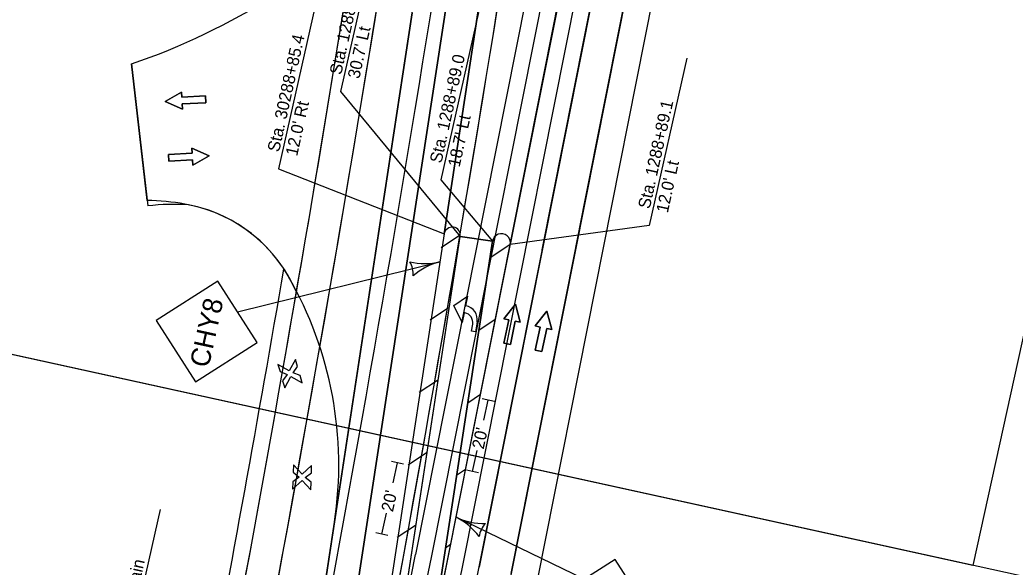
# Model space of a CAD drawing. Extents: x 14104283 to 14120882, y 8635219 to 8671666.
# Drawn here: x 14107792.5 to 14108160.1, y 8639735.9 to 8639938.3 of the extents above; entities that cross this region are included whole.
import ezdxf

# ---------------------------------------------------------------- set-up
doc = ezdxf.new("R2010")
doc.units = 0
for name, color, linetype in [('Cell', 7, 'Continuous'), ('dsnNonPlotable', 7, 'Continuous'), ('dsnPaintExistingBrokenLaneLineWhite', 7, 'Continuous'), ('dsnPaintExistingEdgeLineRightWhite', 7, 'Continuous'), ('dsnPaintPlaceBrokenLaneLineWhite', 7, 'Continuous'), ('dsnPaintPlaceBrokenLaneWhite', 7, 'Continuous'), ('dsnPaintPlaceChannelizingLaneWhite', 7, 'Continuous'), ('dsnPaintPlaceChannelizingLaneYellow', 7, 'Continuous'), ('dsnPaintPlaceEdgeLineRightWhite', 7, 'Continuous'), ('dsnPaintRemoveEdgeLineWhite', 7, 'Continuous'), ('dsnPaintRemoveEdgeLineYellow', 7, 'Continuous'), ('dsnShadingPaved', 7, 'Continuous'), ('dsnStdLabel', 7, 'Continuous'), ('dsnStgShadingPrevPav', 7, 'Continuous'), ('Level 2', 7, 'Continuous'), ('Level 5', 7, 'Continuous'), ('Text', 7, 'Continuous')]:
    doc.layers.add(name, color=color, linetype=linetype)

msp = doc.modelspace()

# ---------------------------------------------------------------- linework, layer by layer
at = {"layer": 'Cell'}
for p, q in [((14107957.11, 8639832.53), (14107957.29, 8639832.5)), ((14107956.89, 8639829.91), (14107956.58, 8639829.95)), ((14107892.01, 8639808.57), (14107887.84, 8639810.89)), ((14107887.84, 8639810.89), (14107888.6, 8639808.24)), ((14107894.33, 8639812.75), (14107892.01, 8639808.57)), ((14107895.09, 8639810.1), (14107894.33, 8639812.75)), ((14107888.6, 8639808.24), (14107891.24, 8639807.18)), ((14107891.24, 8639807.18), (14107889.56, 8639804.88)), ((14107893.4, 8639807.8), (14107895.09, 8639810.1)), ((14107896.05, 8639806.74), (14107893.4, 8639807.8)), ((14107896.81, 8639804.09), (14107896.05, 8639806.74)), ((14107889.56, 8639804.88), (14107890.32, 8639802.24)), ((14107890.32, 8639802.24), (14107892.63, 8639806.41)), ((14107892.63, 8639806.41), (14107896.81, 8639804.09)), ((14107893.54, 8639773.76), (14107893.45, 8639771.01)), ((14107896.8, 8639770.27), (14107893.54, 8639773.76)), ((14107900.29, 8639773.53), (14107896.8, 8639770.27)), ((14107900.2, 8639770.79), (14107900.29, 8639773.53)), ((14107893.45, 8639771.01), (14107895.64, 8639769.19)), ((14107897.89, 8639769.11), (14107900.2, 8639770.79)), ((14107893.24, 8639764.76), (14107896.73, 8639768.02)), ((14107893.33, 8639767.51), (14107893.24, 8639764.76)), ((14107895.64, 8639769.19), (14107893.33, 8639767.51)), ((14107896.73, 8639768.02), (14107899.99, 8639764.54)), ((14107900.08, 8639767.29), (14107897.89, 8639769.11)), ((14107899.99, 8639764.54), (14107900.08, 8639767.29))]:
    msp.add_line(p, q, dxfattribs=at)
for points in [[(14107952.78, 8639832.67), (14107957.86, 8639836.14), (14107957.11, 8639832.53)], [(14107952.78, 8639832.67), (14107957.86, 8639836.14), (14107957.11, 8639832.53)], [(14107956.58, 8639829.95), (14107955.83, 8639826.35), (14107952.78, 8639832.67)], [(14107956.58, 8639829.95), (14107955.83, 8639826.35), (14107952.78, 8639832.67)], [(14107957.11, 8639832.53), (14107957.29, 8639832.5)], [(14107956.89, 8639829.91), (14107956.58, 8639829.95)], [(14107961.41, 8639826.54), (14107960.84, 8639822.91), (14107959.37, 8639823.14), (14107959.77, 8639825.73)], [(14107961.41, 8639826.54), (14107960.84, 8639822.91), (14107959.37, 8639823.14), (14107959.77, 8639825.73)]]:
    msp.add_lwpolyline(points, dxfattribs=at)
for centre, major_axis in [((14107956.49, 8639827.31), (-0.81, -5.19)), ((14107956.49, 8639827.31), (-0.81, -5.19)), ((14107956.32, 8639826.27), (-0.57, -3.64)), ((14107956.32, 8639826.27), (-0.57, -3.64))]:
    msp.add_ellipse(centre, major_axis=major_axis, ratio=0.9474, start_param=1.570796, end_param=3.141593, dxfattribs=at)
at = {"layer": 'dsnNonPlotable'}
for points in [[(14107490.45, 8639880.3), (14107826.84, 8641411.28), (14108813.31, 8641194.53), (14108476.92, 8639663.55)], [(14107651.31, 8639844.94), (14107987.7, 8641375.92), (14108480.93, 8641267.54), (14108144.54, 8639736.56)]]:
    msp.add_lwpolyline(points, close=True, dxfattribs=at)
at = {"layer": 'dsnPaintExistingBrokenLaneLineWhite'}
msp.add_line((14107897.23, 8639597.8), (14108002.8, 8640289.8), dxfattribs=at)
at = {"layer": 'dsnPaintExistingEdgeLineRightWhite'}
msp.add_line((14107908.71, 8639752.63), (14107885.37, 8639599.61), dxfattribs=at)
for centre, radius, start, end in [((14107752.7, 8640158.5), 250, 288.9195, 302.3186), ((14107838.11, 8639781.51), 90, 80.198, 89.1076), ((14107844.07, 8639816), 55, 29.809, 80.198), ((14107770.31, 8639773.74), 140, 351.326, 29.809)]:
    msp.add_arc(centre, radius, start, end, dxfattribs=at)
at = {"layer": 'dsnPaintPlaceBrokenLaneLineWhite'}
msp.add_lwpolyline([(14107985.48, 8639853.32), (14108001.11, 8639932.06), (14108016.73, 8640010.8), (14108028.7, 8640069.55), (14108040.67, 8640128.3), (14108053.24, 8640186.93), (14108065.81, 8640245.56), (14108082.44, 8640321.29), (14108099.08, 8640397.01)], dxfattribs=at)
at = {"layer": 'dsnPaintPlaceBrokenLaneWhite'}
msp.add_lwpolyline([(14107843.64, 8639178.31), (14107884.58, 8639364.68), (14107924.33, 8639550.14), (14107962.2, 8639735.99), (14107989.47, 8639873.39), (14108016.73, 8640010.79)], dxfattribs=at)
at = {"layer": 'dsnPaintPlaceChannelizingLaneWhite'}
for p, q in [((14107944.41, 8639708.12), (14107967.03, 8639856.41)), ((14107973.63, 8639855.23), (14107966.08, 8639850.19)), ((14107968.12, 8639827.49), (14107961.99, 8639823.39)), ((14107962.62, 8639799.75), (14107957.91, 8639796.59)), ((14107957.11, 8639772), (14107953.82, 8639769.8)), ((14107951.61, 8639744.26), (14107949.73, 8639743))]:
    msp.add_line(p, q, dxfattribs=at)
msp.add_lwpolyline([(14107944.41, 8639708.12), (14107950.42, 8639738.27), (14107973.63, 8639855.23)], dxfattribs=at)
msp.add_arc((14107970.34, 8639855.88), 3.35, 348.776, 171.0218, dxfattribs=at)
at = {"layer": 'dsnPaintPlaceChannelizingLaneYellow'}
for p, q in [((14107898.55, 8639487.12), (14107955.17, 8639858.22)), ((14107949.23, 8639859.12), (14107909.09, 8639595.99)), ((14107954.94, 8639858.56), (14107948.17, 8639854.04)), ((14107950.85, 8639831.77), (14107944.08, 8639827.24)), ((14107946.76, 8639804.97), (14107939.99, 8639800.45)), ((14107942.67, 8639778.18), (14107935.91, 8639773.65)), ((14107938.59, 8639751.38), (14107931.82, 8639746.86))]:
    msp.add_line(p, q, dxfattribs=at)
msp.add_arc((14107952.2, 8639858.67), 3, 351.326, 171.326, dxfattribs=at)
at = {"layer": 'dsnPaintPlaceEdgeLineRightWhite'}
msp.add_line((14107973.96, 8639733.6), (14107997.25, 8639850.98), dxfattribs=at)
msp.add_lwpolyline([(14107997.25, 8639850.98), (14108001.23, 8639871.02), (14108028.5, 8640008.43), (14108052.42, 8640125.85), (14108077.53, 8640243.01), (14108094.16, 8640318.73), (14108110.8, 8640394.44)], dxfattribs=at)
at = {"layer": 'dsnPaintRemoveEdgeLineWhite'}
msp.add_lwpolyline([(14107811.17, 8639057.08), (14107844.94, 8639211.53), (14107878.72, 8639365.97), (14107918.46, 8639551.34), (14107956.3, 8639737.1), (14108010.84, 8640011.94), (14108059.95, 8640246.87), (14108093.19, 8640398.18)], dxfattribs=at)
at = {"layer": 'dsnPaintRemoveEdgeLineYellow'}
msp.add_lwpolyline([(14107799.44, 8639059.65), (14107867, 8639368.55), (14107944.53, 8639739.44), (14107999.07, 8640014.27), (14108048.23, 8640249.45), (14108081.5, 8640400.87)], dxfattribs=at)
at = {"layer": 'dsnShadingPaved'}
for p, q in [((14107885.37, 8639599.61), (14107990.94, 8640291.61)), ((14108002.8, 8640289.8), (14107897.23, 8639597.8)), ((14108004.96, 8640013.11), (14107973.63, 8639855.23)), ((14107897.23, 8639597.8), (14107955.22, 8639977.91)), ((14107949.24, 8639859.12), (14107967.08, 8639976.1)), ((14107967.08, 8639976.1), (14107949.24, 8639859.12)), ((14107937.44, 8639940.91), (14107908.71, 8639752.63)), ((14107839.51, 8639871.5), (14107833.76, 8639922)), ((14107897.98, 8639483.38), (14107955.17, 8639858.22)), ((14107949.23, 8639859.12), (14107909.09, 8639595.99)), ((14107967.03, 8639856.41), (14107955.17, 8639858.22)), ((14107955.17, 8639858.22), (14107967.03, 8639856.41)), ((14107967.03, 8639856.41), (14107944.41, 8639708.12))]:
    msp.add_line(p, q, dxfattribs=at)
for points in [[(14107831.92, 8639180.86), (14107872.85, 8639367.2), (14107912.58, 8639552.57), (14107950.43, 8639738.33), (14108004.96, 8640013.11)], [(14108028.5, 8640008.43), (14107973.96, 8639733.6), (14107936.08, 8639547.66), (14107896.3, 8639362.11), (14107855.36, 8639175.71)]]:
    msp.add_lwpolyline(points, dxfattribs=at)
for centre, radius, start, end in [((14107752.7, 8640158.5), 250, 288.9195, 302.3186), ((14107838.11, 8639781.51), 90, 80.198, 89.1076), ((14107844.07, 8639816), 55, 29.809, 80.198), ((14107952.2, 8639858.67), 3, 351.326, 171.326), ((14107970.34, 8639855.88), 3.35, 348.776, 171.0218), ((14107770.31, 8639773.74), 140, 351.326, 29.809)]:
    msp.add_arc(centre, radius, start, end, dxfattribs=at)
at = {"layer": 'dsnStdLabel'}
for p, q in [((14107872.9, 8639830.31), (14107947.66, 8639848.82)), ((14108000.99, 8639731.5), (14107953.61, 8639754.35))]:
    msp.add_line(p, q, dxfattribs=at)
for points in [[(14107857.43, 8639804.39), (14107880.18, 8639818.94), (14107865.63, 8639841.69), (14107842.88, 8639827.14)], [(14108004.17, 8639701.48), (14108026.91, 8639716.03), (14108012.36, 8639738.77), (14107989.62, 8639724.22)]]:
    msp.add_lwpolyline(points, close=True, dxfattribs=at)
for centre, radius, start, end in [((14107942.14, 8639871.1), 22.95, 255.8346, 283.9059), ((14107928.98, 8639844.2), 8.86, 356.1715, 31.64), ((14107953.17, 8639826.54), 22.95, 103.9057, 131.977), ((14107943.64, 8639733.68), 22.95, 36.1773, 64.2486), ((14107963.58, 8639775.02), 22.95, 244.2484, 272.3197), ((14107970.94, 8639745.99), 8.86, 136.5142, 171.9827)]:
    msp.add_arc(centre, radius, start, end, dxfattribs=at)
at = {"layer": 'dsnStgShadingPrevPav'}
for p, q in [((14107993.19, 8640015.44), (14107938.65, 8639740.6)), ((14107993.19, 8640015.44), (14107938.65, 8639740.6)), ((14107950.42, 8639738.27), (14108004.96, 8640013.11)), ((14108016.73, 8640010.77), (14107962.19, 8639735.93)), ((14108016.73, 8640010.77), (14107962.19, 8639735.93)), ((14107983.77, 8639731.65), (14108038.31, 8640006.49)), ((14107950.42, 8639738.27), (14107992.68, 8639951.24)), ((14107833.76, 8639922), (14107839.82, 8639869.51))]:
    msp.add_line(p, q, dxfattribs=at)
for centre, radius, start, end in [((14098576.76, 8641447.78), 9468, 347.807255, 351.672846), ((14098576.76, 8641447.78), 9456, 348.449343, 351.672846), ((14098576.76, 8641447.78), 9468, 348.194582, 351.672846), ((14098576.76, 8641447.78), 9488, 348.202524, 351.672846), ((14098576.76, 8641447.78), 9488, 348.202524, 351.672846), ((14098576.76, 8641447.78), 9512, 348.176197, 351.653537), ((14098576.76, 8641447.78), 9512, 348.212012, 351.653537), ((14098576.76, 8641447.78), 9456, 350.195701, 351.23682), ((14107752.7, 8640158.5), 250, 288.9195, 302.3186), ((14107849.81, 8639782.85), 87.24, 86.7296, 96.5795), ((14107844.07, 8639816), 55, 23.1027, 78.7566), ((14098576.76, 8641447.78), 9450, 348.220778, 350.242299), ((14107844.07, 8639816), 55, 23.1027, 33.2753), ((14098576.76, 8641447.78), 9456, 348.449343, 350.195701), ((14089678.7, 8643364.11), 18616, 348.014807, 348.776036), ((14089678.7, 8643364.11), 18616, 348.014807, 348.776036), ((14089678.7, 8643364.11), 18628, 347.714997, 348.776036), ((14089678.7, 8643364.11), 18628, 347.714933, 348.776036)]:
    msp.add_arc(centre, radius, start, end, dxfattribs=at)
at = {"layer": 'Level 2'}
for points in [[(14107861.24, 8639907.67), (14107861.11, 8639910.16), (14107852.37, 8639909.7), (14107852.27, 8639911.57), (14107846.19, 8639908.12), (14107852.6, 8639905.33), (14107852.5, 8639907.2)], [(14107847.44, 8639888.53), (14107847.57, 8639886.03), (14107856.31, 8639886.5), (14107856.41, 8639884.62), (14107862.49, 8639888.08), (14107856.08, 8639890.86), (14107856.18, 8639888.99)], [(14107971.24, 8639818.81), (14107973.69, 8639818.29), (14107975.5, 8639826.85), (14107977.34, 8639826.46), (14107975.57, 8639833.22), (14107971.22, 8639827.76), (14107973.06, 8639827.37)], [(14107982.87, 8639816.15), (14107985.32, 8639815.63), (14107987.13, 8639824.19), (14107988.96, 8639823.8), (14107987.2, 8639830.57), (14107982.85, 8639825.1), (14107984.68, 8639824.71)]]:
    msp.add_lwpolyline(points, close=True, dxfattribs=at)
at = {"layer": 'Level 5'}
for points in [[(14107852.5, 8639907.2), (14107852.6, 8639905.33), (14107846.19, 8639908.12), (14107852.27, 8639911.57), (14107852.37, 8639909.7), (14107861.11, 8639910.16), (14107861.24, 8639907.67), (14107852.5, 8639907.2)], [(14107856.18, 8639888.99), (14107856.08, 8639890.86), (14107862.49, 8639888.08), (14107856.41, 8639884.62), (14107856.31, 8639886.5), (14107847.57, 8639886.03), (14107847.44, 8639888.53), (14107856.18, 8639888.99)], [(14107973.06, 8639827.37), (14107971.22, 8639827.76), (14107975.57, 8639833.22), (14107977.34, 8639826.46), (14107975.5, 8639826.85), (14107973.69, 8639818.29), (14107971.24, 8639818.81), (14107973.06, 8639827.37)], [(14107984.68, 8639824.71), (14107982.85, 8639825.1), (14107987.2, 8639830.57), (14107988.96, 8639823.8), (14107987.13, 8639824.19), (14107985.32, 8639815.63), (14107982.87, 8639816.15), (14107984.68, 8639824.71)]]:
    msp.add_lwpolyline(points, dxfattribs=at)
at = {"layer": 'Text'}
for p, q in [((14107967.76, 8639797.22), (14107963.3, 8639798.2)), ((14107963.89, 8639790.26), (14107965.53, 8639797.71)), ((14107959.72, 8639771.29), (14107961.44, 8639779.09)), ((14107934.27, 8639774.01), (14107929.81, 8639774.99)), ((14107930.4, 8639767.05), (14107932.04, 8639774.5)), ((14107961.95, 8639770.8), (14107957.49, 8639771.78)), ((14107926.23, 8639748.09), (14107927.94, 8639755.88)), ((14107928.46, 8639747.6), (14107924, 8639748.58))]:
    msp.add_line(p, q, dxfattribs=at)
for points in [[(14107924.93, 8639973.66), (14107910.94, 8639911.81), (14107955.17, 8639858.22)], [(14107902.87, 8639949), (14107888, 8639883.25), (14107949.23, 8639859.12)], [(14107961.95, 8639940.98), (14107947.97, 8639879.13), (14107967.03, 8639856.41)], [(14108038.88, 8639924.08), (14108024.9, 8639862.23), (14107973.63, 8639855.23)], [(14107844.39, 8639757.3), (14107828.16, 8639685.56), (14107876.64, 8639636.14)]]:
    msp.add_lwpolyline(points, dxfattribs=at)

# ---------------------------------------------------------------- texts
at = {"layer": 'dsnStdLabel'}
msp.add_text('CHY8', height=7.2, rotation=77.6078, dxfattribs=at).set_placement((14107862.22, 8639809.38))
at = {"layer": 'Text'}
for s, height, p in [('Sta. 1288+89.0', 4.4845, (14107911.2, 8639917.75)), ("30.7' Lt", 4.484, (14107917.88, 8639916.28)), ('Sta. 30288+85.4', 4.4845, (14107888.26, 8639889.19)), ('Sta. 1288+89.0', 4.4845, (14107948.22, 8639885.07)), ("12.0' Rt", 4.484, (14107894.94, 8639887.72)), ('Sta. 1288+89.1', 4.4845, (14108025.15, 8639868.17)), ("18.7' Lt", 4.484, (14107954.91, 8639883.6)), ("12.0' Lt", 4.484, (14108031.83, 8639866.7)), ("20'", 4.484, (14107963.78, 8639779.32)), ("20'", 4.484, (14107930.29, 8639756.12)), ('Barrels to Remain', 4.4845, (14107828.4, 8639691.44))]:
    msp.add_text(s, height=height, rotation=77.6078, dxfattribs=at).set_placement(p)

doc.saveas('drawing.dxf')
